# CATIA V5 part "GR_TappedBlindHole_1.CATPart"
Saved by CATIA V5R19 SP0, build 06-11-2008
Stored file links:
  C:\Program Files\Dassault Systemes\Power Feature\SampleData\GeneralData\GeometricalRules\GeomRuleParts\GR_TappedBlindHole_1.CATPart
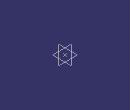
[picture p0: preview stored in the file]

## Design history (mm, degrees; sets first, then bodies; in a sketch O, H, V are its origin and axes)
Set1
  Point1: (0, 0, 0)
Body1 (main body)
